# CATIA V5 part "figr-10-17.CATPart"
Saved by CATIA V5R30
Part number: Part1
Bounding box of the stored display mesh (mm): x -29.811 to 29.811, y 0 to 29.811, z -21.213 to 21.213
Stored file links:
  D:\PROJECTS\CATIA V56R 2020\Resources\Parts File\c10_catia_v5_6r2020_prt\figr-10-17.CATPart
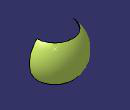
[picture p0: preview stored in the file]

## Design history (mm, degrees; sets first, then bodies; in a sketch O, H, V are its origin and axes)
Set1
  Point1: (0, 0, 0)
  Sphere1: Center Point1, Radius 30, Para1 -45, Para3 0, Para4 180
Body1 (main body)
